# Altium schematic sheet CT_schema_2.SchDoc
size 362 x 192 mm
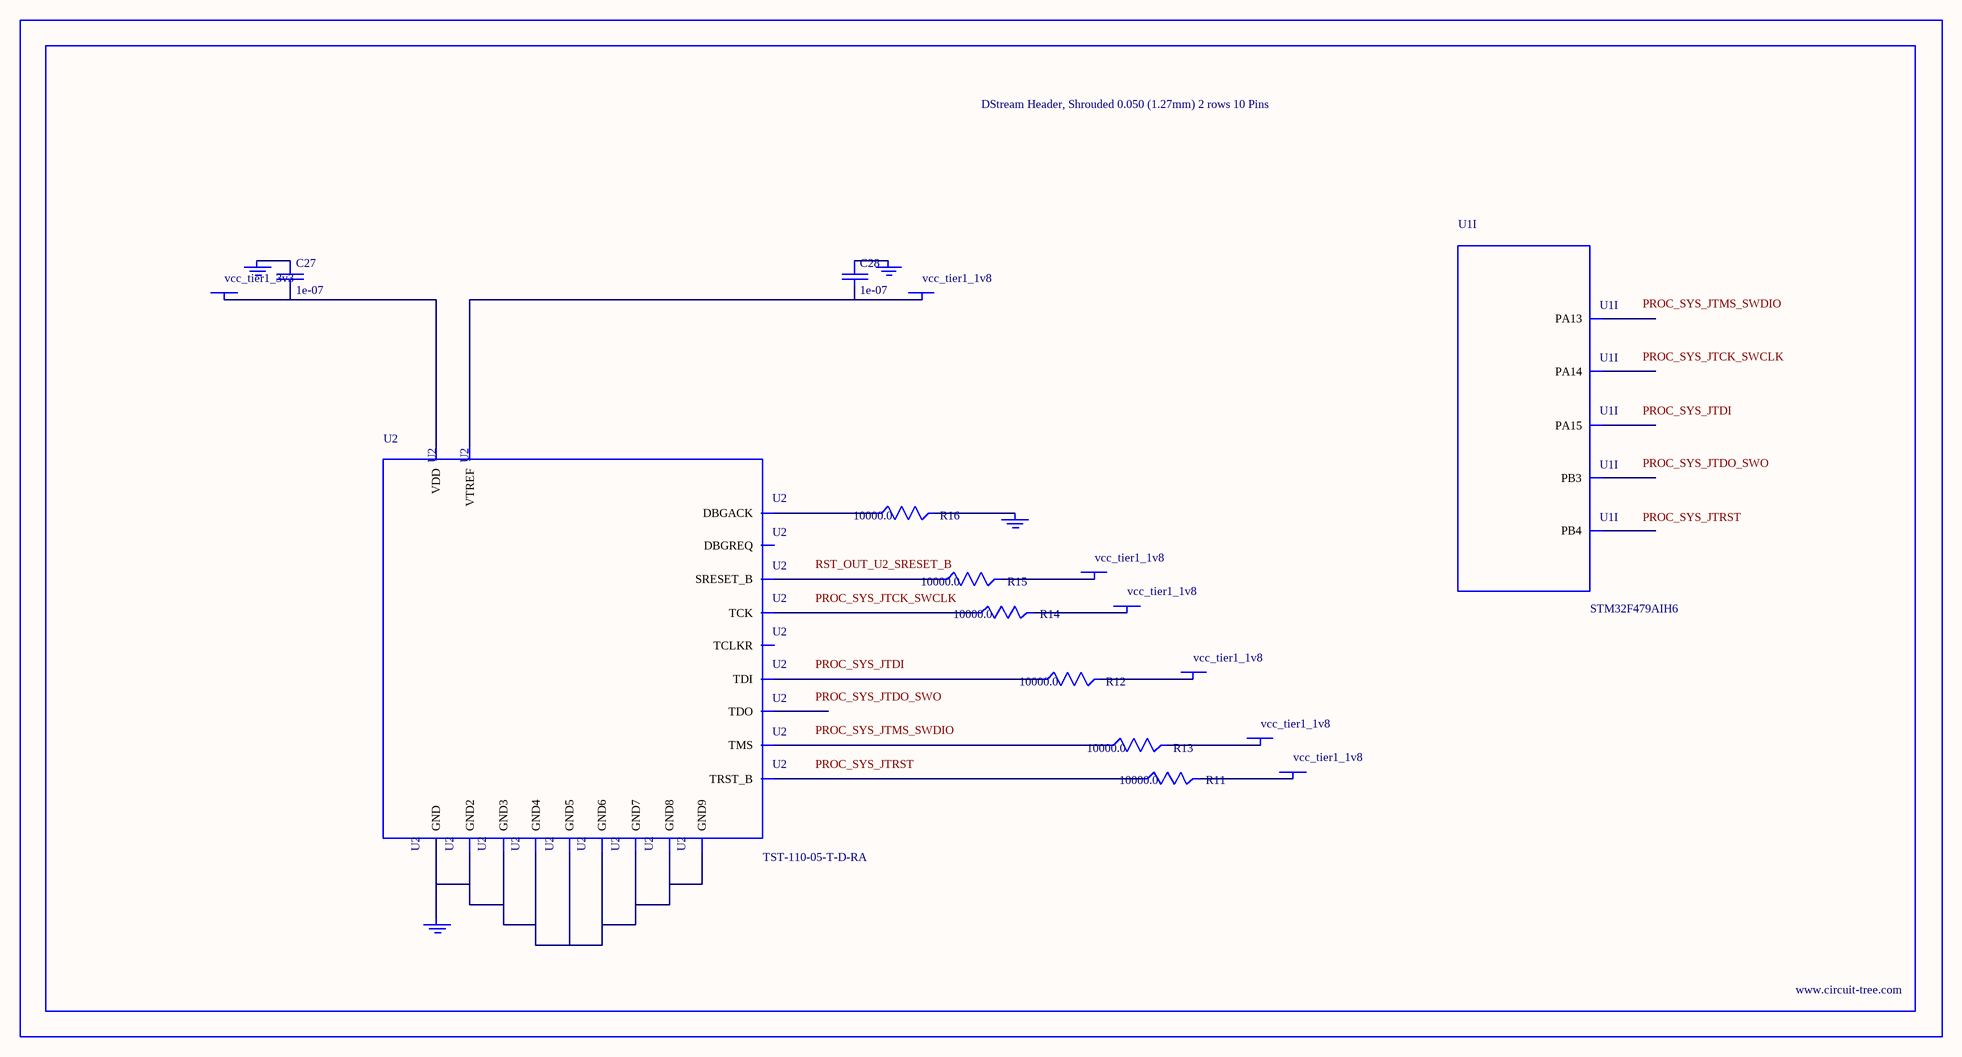
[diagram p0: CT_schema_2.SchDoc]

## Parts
BORDER1  (no value)
C27  1e-07  [C0402]
C28  1e-07  [C0402]
GND_INSTANCE_1_0  (no value)
GND_INSTANCE_1_1  (no value)
GND_INSTANCE_1_2  (no value)
GND_INSTANCE_1_3  (no value)
POWER_INSTANCE_1_0  vcc_tier1_1v8
POWER_INSTANCE_1_1  vcc_tier1_3v3
POWER_INSTANCE_1_2  vcc_tier1_1v8
POWER_INSTANCE_1_3  vcc_tier1_1v8
POWER_INSTANCE_1_4  vcc_tier1_1v8
POWER_INSTANCE_1_5  vcc_tier1_1v8
POWER_INSTANCE_1_6  vcc_tier1_1v8
R11  10000.0  [R0603]
R12  10000.0  [R0603]
R13  10000.0  [R0603]
R14  10000.0  [R0603]
R15  10000.0  [R0603]
R16  10000.0  [R0603]
U1  STM32F479AIH6  [UFBGA169]  (part I of 14)
U2  TST-110-05-T-D-RA  [TST-110-05-T-D-RA]

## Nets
NetC27_1: C27.1 GND_INSTANCE_1_1.0(GND)
NetC27_2: C27.2 POWER_INSTANCE_1_1.0(PWR) U2.2(VDD)
NetC28_1: C28.1 GND_INSTANCE_1_0.0(GND)
NetC28_2: C28.2 POWER_INSTANCE_1_0.0(PWR) U2.1(VTREF)
NetGND_INSTANCE_1_2_0: GND_INSTANCE_1_2.0(GND) R16.2
NetGND_INSTANCE_1_3_0: GND_INSTANCE_1_3.0(GND) U2.4(GND) U2.6(GND2) U2.8(GND3) U2.10(GND4) U2.12(GND5) U2.14(GND6) U2.16(GND7) U2.18(GND8) U2.20(GND9)
NetPOWER_INSTANCE_1_2_0: POWER_INSTANCE_1_2.0(PWR) R11.2
NetPOWER_INSTANCE_1_3_0: POWER_INSTANCE_1_3.0(PWR) R12.2
NetPOWER_INSTANCE_1_4_0: POWER_INSTANCE_1_4.0(PWR) R13.2
NetPOWER_INSTANCE_1_5_0: POWER_INSTANCE_1_5.0(PWR) R14.2
NetPOWER_INSTANCE_1_6_0: POWER_INSTANCE_1_6.0(PWR) R15.2
NetR11_1: R11.1 U2.3(TRST_B)
NetR12_1: R12.1 U2.5(TDI)
NetR13_1: R13.1 U2.7(TMS)
NetR14_1: R14.1 U2.9(TCK)
NetR15_1: R15.1 U2.15(SRESET_B)
NetR16_1: R16.1 U2.19(DBGACK)

Not connected (* = marked no-connect by the designer): U1 A10(PA14) A11(PA13) B5(PB3) B11(PA15) D6(PB4); U2 11(TCLKR) 13(TDO) 17(DBGREQ)

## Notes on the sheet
- Labels drawn without touching a wire or pin: PROC_SYS_JTCK_SWCLK, PROC_SYS_JTDI, PROC_SYS_JTDO_SWO, PROC_SYS_JTMS_SWDIO, PROC_SYS_JTRST, RST_OUT_U2_SRESET_B

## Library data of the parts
BORDER1 = BORDER_PAGE1
C27 C28 = C0402C104K3RACTU
GND_INSTANCE_1_0-GND_INSTANCE_1_3 = GND
POWER_INSTANCE_1_0-POWER_INSTANCE_1_6 = PWR
R11-R16 = RC0603JR-0710KL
